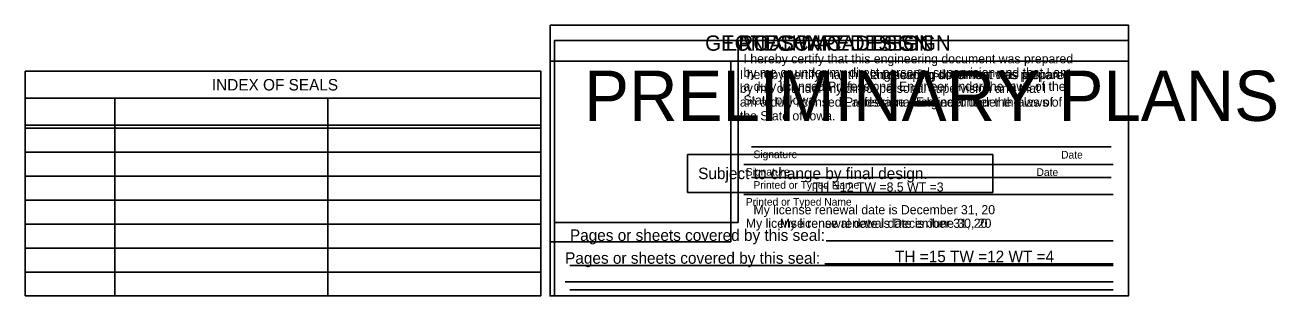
# Model space of a CAD drawing. Extents: x 10196 to 23010, y 6417 to 10189.
# Drawn here: x 11806 to 13441, y 7973 to 8327 of the extents above; entities that cross this region are included whole.
import ezdxf

# ---------------------------------------------------------------- set-up
doc = ezdxf.new("R2010")
doc.units = 0
for name, color, linetype in [('Level 12', 7, 'Continuous'), ('Level 14', 7, 'Continuous'), ('Level 2', 7, 'Continuous'), ('Level 20', 7, 'Continuous'), ('Level 21', 7, 'Continuous'), ('Level 22', 7, 'Continuous'), ('Level 3', 7, 'Continuous'), ('Level 61', 7, 'Continuous')]:
    doc.layers.add(name, color=color, linetype=linetype)

msp = doc.modelspace()

# ---------------------------------------------------------------- linework, layer by layer
at = {"layer": 'Level 12'}
for p, q in [((12737.9, 8069.1), (12737.9, 8307)), ((13225.5, 8167.9), (12755.5, 8167.9)), ((13225.5, 8127.9), (12755.5, 8127.9)), ((12497.9, 8069.1), (12737.9, 8069.1)), ((12852.9, 8044.9), (13227.9, 8044.9)), ((12518, 8012.9), (13227.9, 8012.9)), ((12518, 7980.9), (13227.9, 7980.9))]:
    msp.add_line(p, q, dxfattribs=at)
msp.add_lwpolyline([(12497.9, 8307), (13247.9, 8307), (13247.9, 7972.9), (12497.9, 7972.9)], close=True, dxfattribs=at)
at = {"layer": 'Level 14'}
for p, q in [((11805.8, 8266.8), (12479.8, 8266.8)), ((11805.8, 7972.9), (11805.8, 8266.8)), ((12479.8, 8266.8), (12479.8, 7972.9)), ((11805.8, 8231.5), (12479.8, 8231.5)), ((11923.4, 8231.5), (11923.4, 7972.9)), ((12201.6, 8231.5), (12201.6, 7972.9)), ((11805.8, 8196.2), (12479.8, 8196.2)), ((11805.8, 8192.3), (12479.8, 8192.3)), ((11805.8, 8161), (12479.8, 8161)), ((11805.8, 8129.6), (12479.8, 8129.6)), ((11805.8, 8098.3), (12479.8, 8098.3)), ((11805.8, 8066.9), (12479.8, 8066.9)), ((12479.8, 8035.6), (11805.8, 8035.6)), ((12479.8, 8004.2), (11805.8, 8004.2)), ((12479.8, 7972.9), (11805.8, 7972.9))]:
    msp.add_line(p, q, dxfattribs=at)
at = {"layer": 'Level 2'}
for p, q in [((12671.6, 8108.3), (12671.6, 8158)), ((12671.6, 8158), (13070.8, 8158)), ((13070.8, 8158), (13070.8, 8108.3)), ((13070.8, 8108.3), (12671.6, 8108.3))]:
    msp.add_line(p, q, dxfattribs=at)
at = {"layer": 'Level 20'}
for p, q in [((12492, 8280), (13247.9, 8280)), ((12728.2, 8043.7), (12728.2, 8280)), ((13228.2, 8144.9), (12745.5, 8144.9)), ((13228.2, 8105.5), (12745.5, 8105.5)), ((12492, 8043.7), (12728.2, 8043.7)), ((12853.2, 8015), (13228.2, 8015)), ((12511.7, 7991.3), (13228.2, 7991.3))]:
    msp.add_line(p, q, dxfattribs=at)
msp.add_lwpolyline([(12492, 8327.2), (13247.9, 8327.2), (13247.9, 7972.9), (12492, 7972.9)], close=True, dxfattribs=at)
at = {"layer": 'Level 21'}
for p, q in [((12492, 8280), (13247.9, 8280)), ((12728.2, 8043.7), (12728.2, 8280)), ((13228.2, 8144.9), (12745.5, 8144.9)), ((13228.2, 8105.5), (12745.5, 8105.5)), ((12492, 8043.7), (12728.2, 8043.7)), ((12851.2, 8015), (13228.2, 8015)), ((12511.7, 7991.3), (13228.2, 7991.3))]:
    msp.add_line(p, q, dxfattribs=at)
msp.add_lwpolyline([(12492, 8327.2), (13247.9, 8327.2), (13247.9, 7972.9), (12492, 7972.9)], close=True, dxfattribs=at)
at = {"layer": 'Level 22'}
for p, q in [((12492, 8280), (13247.9, 8280)), ((12728.2, 8043.7), (12728.2, 8280)), ((13228.2, 8144.9), (12745.5, 8144.9)), ((13228.2, 8105.5), (12745.5, 8105.5)), ((12492, 8043.7), (12728.2, 8043.7)), ((12851.2, 8015), (13228.2, 8015)), ((12511.7, 7991.3), (13228.2, 7991.3))]:
    msp.add_line(p, q, dxfattribs=at)
msp.add_lwpolyline([(12492, 8327.2), (13247.9, 8327.2), (13247.9, 7972.9), (12492, 7972.9)], close=True, dxfattribs=at)
at = {"layer": 'Level 3'}
msp.add_lwpolyline([(13247.9, 7972.9), (12497.9, 7972.9), (12497.9, 8307), (13247.9, 8307)], close=True, dxfattribs=at)

# ---------------------------------------------------------------- texts
at = {"layer": 'Level 12'}
for s, height, p in [('I hereby certify that this engineering document was prepared', 12, (12744.8, 8277.1)), ('by me or under my direct personal supervision and that I am', 12, (12744.8, 8259.1)), ('a duly licensed Professional Engineer under the laws of the', 12, (12744.8, 8241.1)), ('State of Iowa.', 12, (12744.8, 8223.1)), ('Signature', 10, (12757.9, 8153.1)), ('Date', 10, (13160, 8152.6)), ('Printed or Typed Name', 10, (12757.9, 8113.1)), ('My license renewal date is December 31, 20', 12, (12757.9, 8079.7)), ('Pages or sheets covered by this seal:', 15, (12518, 8044.9))]:
    msp.add_text(s, height=height, dxfattribs=at).set_placement(p)
at = {"layer": 'Level 14'}
msp.add_text('INDEX OF SEALS', height=15, dxfattribs=at).set_placement((12050, 8241.6))
at = {"layer": 'Level 2'}
for s, height, p in [('PRELIMINARY PLANS', 65.706, (12536.6, 8201.8)), ('Subject to change by final design.', 15, (12685.6, 8125.7))]:
    msp.add_text(s, height=height, dxfattribs=at).set_placement(p)
at = {"layer": 'Level 20'}
for s, height, p in [('ROADWAY DESIGN', 20, (12738.3, 8293.6)), ('I hereby certify that this engineering document was prepared', 12, (12740.1, 8256.5)), ('by me or under my direct personal supervision and that I', 12, (12740.1, 8238.5)), ('am a duly licensed Professional Engineer under the laws of', 12, (12740.1, 8220.5)), ('the State of Iowa.', 12, (12740.1, 8202.5)), ('Signature', 10, (12747.9, 8130.3)), ('Date', 10, (13127.9, 8129.8)), ('Printed or Typed Name', 10, (12747.9, 8091)), ('My license renewal date is December 31, 20', 12, (12747.9, 8062)), ('Pages or sheets covered by this seal:', 15, (12511.7, 8015))]:
    msp.add_text(s, height=height, dxfattribs=at).set_placement(p)
at = {"layer": 'Level 21'}
for s, height, p in [('GEOTECHNICAL DESIGN', 20, (12694.7, 8293.6)), ('I hereby certify that this engineering document was prepared', 12, (12740.1, 8256.5)), ('by me or under my direct personal supervision and that I', 12, (12740.1, 8238.5)), ('am a duly licensed Professional Engineer under the laws of', 12, (12740.1, 8220.5)), ('the State of Iowa.', 12, (12740.1, 8202.5)), ('Signature', 10, (12747.9, 8130.3)), ('Date', 10, (13127.9, 8129.8)), ('Printed or Typed Name', 10, (12747.9, 8091)), ('My license renewal date is December 31, 20', 12, (12747.9, 8062)), ('Pages or sheets covered by this seal:', 15, (12511.7, 8015))]:
    msp.add_text(s, height=height, dxfattribs=at).set_placement(p)
at = {"layer": 'Level 22'}
for s, height, p in [('LANDSCAPE DESIGN', 20, (12721.5, 8293.6)), ('I hereby certify that this landscaping document was prepared', 12, (12740.1, 8256.5)), ('by me or under my direct personal supervision and that I', 12, (12740.1, 8238.5)), ('am a duly licensed Landscape Architect under the laws of', 12, (12740.1, 8220.5)), ('the State of Iowa.', 12, (12740.1, 8202.5)), ('Signature', 10, (12747.9, 8130.3)), ('Date', 10, (13127.9, 8129.8)), ('Printed or Typed Name', 10, (12747.9, 8091)), ('My license renewal date is June 30, 20', 12, (12792.4, 8062)), ('Pages or sheets covered by this seal:', 15, (12511.7, 8015))]:
    msp.add_text(s, height=height, dxfattribs=at).set_placement(p)
at = {"layer": 'Level 61'}
for s, height, p in [('TH =12 TW =8.5 WT =3', 12, (12835.6, 8109.4)), ('TH =15 TW =12 WT =4', 15, (12942.9, 8017.1))]:
    msp.add_text(s, height=height, dxfattribs=at).set_placement(p)

doc.saveas('drawing.dxf')
